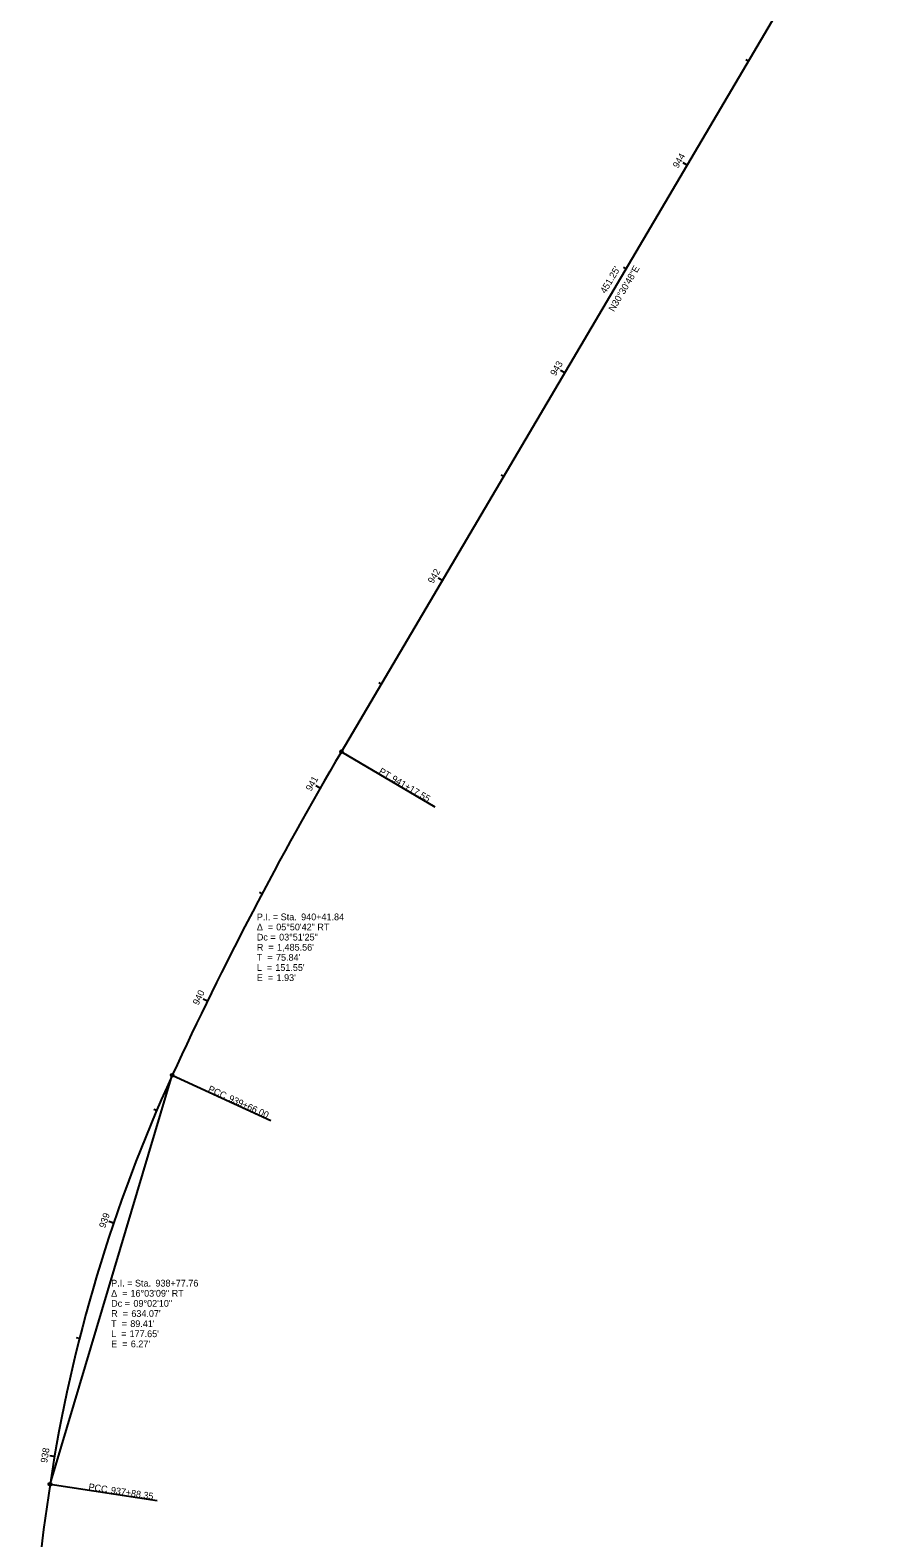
# Model space of a CAD drawing. Extents: x 1978725 to 1979446, y 230316 to 232755.
# Drawn here: x 1978788 to 1979146, y 231522 to 232148 of the extents above; entities that cross this region are included whole.
import ezdxf

# ---------------------------------------------------------------- set-up
doc = ezdxf.new("R2010")
doc.units = 0
for name, color, linetype in [('GE_X_Alignment', 7, 'Continuous'), ('GE_X_Alignment_1000_Curve_Data', 7, 'Continuous'), ('GE_X_Alignment_1000_Stations', 7, 'Continuous'), ('GE_X_Alignment_100_Curve_Data', 7, 'Continuous'), ('GE_X_Alignment_100_Stations', 7, 'Continuous'), ('GE_X_Alignment_500_Curve_Data', 7, 'Continuous'), ('GE_X_Alignment_500_Stations', 7, 'Continuous'), ('SC_Scratch1', 7, 'Continuous')]:
    doc.layers.add(name, color=color, linetype=linetype)

msp = doc.modelspace()

# ---------------------------------------------------------------- linework, layer by layer
at = {"layer": 'GE_X_Alignment'}
msp.add_line((1978917.16, 231848.52), (1979146.28, 232237.28), dxfattribs=at)
for centre, radius, start, end in [((1980196.99, 231094.24), 1485.56, 149.48656, 155.33165), ((1979423.21, 231449.62), 634.07, 155.33165, 171.38409), ((1979695.72, 231408.33), 909.69, 171.38409, 176.17086)]:
    msp.add_arc(centre, radius, start, end, dxfattribs=at)
at = {"layer": 'GE_X_Alignment_1000_Stations'}
for p, q in [((1978917.16, 231848.52), (1978955.93, 231825.67)), ((1978861.55, 231745), (1978859.75, 231745.87)), ((1978847, 231714.26), (1978887.9, 231695.48)), ((1978796.29, 231544.61), (1978840.78, 231537.87))]:
    msp.add_line(p, q, dxfattribs=at)
for centre in [(1978917.16, 231848.52), (1978847, 231714.26), (1978796.29, 231544.61)]:
    msp.add_circle(centre, 0.6, dxfattribs=at)
at = {"layer": 'GE_X_Alignment_100_Stations'}
for p, q in [((1979085.96, 232134.93), (1979084.93, 232135.54)), ((1979060.58, 232091.85), (1979058.85, 232092.87)), ((1979035.19, 232048.78), (1979034.15, 232049.39)), ((1979009.8, 232005.7), (1979008.08, 232006.72)), ((1978984.41, 231962.63), (1978983.38, 231963.24)), ((1978959.03, 231919.55), (1978957.3, 231920.57)), ((1978933.64, 231876.48), (1978932.61, 231877.09)), ((1978917.16, 231848.52), (1978955.93, 231825.67)), ((1978908.34, 231833.35), (1978906.61, 231834.34)), ((1978884.2, 231789.57), (1978883.14, 231790.13)), ((1978861.55, 231745), (1978859.75, 231745.87)), ((1978847, 231714.26), (1978887.9, 231695.48)), ((1978840.51, 231699.64), (1978839.41, 231700.11)), ((1978822.63, 231652.96), (1978820.73, 231653.6)), ((1978808.47, 231605.02), (1978807.31, 231605.31)), ((1978798.14, 231556.11), (1978796.17, 231556.45)), ((1978796.29, 231544.61), (1978840.78, 231537.87))]:
    msp.add_line(p, q, dxfattribs=at)
for centre in [(1978917.16, 231848.52), (1978847, 231714.26), (1978796.29, 231544.61)]:
    msp.add_circle(centre, 0.6, dxfattribs=at)
at = {"layer": 'GE_X_Alignment_500_Stations'}
for p, q in [((1979060.58, 232091.85), (1979059.54, 232092.46)), ((1979009.8, 232005.7), (1979008.77, 232006.31)), ((1978959.03, 231919.55), (1978957.99, 231920.16)), ((1978917.16, 231848.52), (1978955.93, 231825.67)), ((1978908.34, 231833.35), (1978907.3, 231833.95)), ((1978861.55, 231745), (1978859.75, 231745.87)), ((1978847, 231714.26), (1978887.9, 231695.48)), ((1978822.63, 231652.96), (1978821.49, 231653.35)), ((1978798.14, 231556.11), (1978796.96, 231556.31)), ((1978796.29, 231544.61), (1978840.78, 231537.87))]:
    msp.add_line(p, q, dxfattribs=at)
for centre in [(1978917.16, 231848.52), (1978847, 231714.26), (1978796.29, 231544.61)]:
    msp.add_circle(centre, 0.6, dxfattribs=at)
at = {"layer": 'SC_Scratch1'}
msp.add_line((1978796.29, 231544.61), (1978847, 231714.26), dxfattribs=at)

# ---------------------------------------------------------------- texts
at = {"layer": 'GE_X_Alignment_1000_Curve_Data'}
for s, p in [('P.I. = Sta. ', (1978882.08, 231778.59)), ('940+41.84', (1978900.45, 231778.59)), ('Δ  = ', (1978882.08, 231774.39)), ('Dc = ', (1978882.08, 231770.19)), ('05°50\'42" RT', (1978890.11, 231774.39)), ('03°51\'25"', (1978891.32, 231770.19)), ('R  = ', (1978882.08, 231765.99)), ("1,485.56'", (1978890.45, 231765.99)), ('T  = ', (1978882.08, 231761.79)), ('L  = ', (1978882.08, 231757.59)), ("151.55'", (1978889.73, 231757.59)), ("75.84'", (1978890.02, 231761.79)), ('E  = ', (1978882.08, 231753.39)), ("1.93'", (1978890.24, 231753.39)), ('P.I. = Sta. ', (1978821.65, 231626.64)), ('938+77.76', (1978840.02, 231626.64)), ('Δ  = ', (1978821.65, 231622.44)), ('16°03\'09" RT', (1978829.67, 231622.44)), ('Dc = ', (1978821.65, 231618.24)), ('R  = ', (1978821.65, 231614.04)), ("634.07'", (1978830.02, 231614.04)), ('09°02\'10"', (1978830.89, 231618.24)), ('T  = ', (1978821.65, 231609.84)), ("89.41'", (1978829.58, 231609.84)), ('L  = ', (1978821.65, 231605.64)), ('E  = ', (1978821.65, 231601.44)), ("177.65'", (1978829.29, 231605.64)), ("6.27'", (1978829.8, 231601.44))]:
    msp.add_text(s, height=2.8, dxfattribs=at).set_placement(p)
at = {"layer": 'GE_X_Alignment_1000_Stations'}
for s, rotation, p in [("451.25'", 59.48656, (1979026.71, 232038.33)), ('N30°30\'48"E', 59.48656, (1979030.18, 232030.83)), ('PT', 329.48656, (1978932.37, 231839.61)), ('941+17.55', 329.48656, (1978937.62, 231836.52)), ('940', 64.02027, (1978857.82, 231743.16)), ('PCC', 335.33165, (1978861.57, 231707.62)), ('939+66.00', 335.33165, (1978870.07, 231703.72)), ('PCC', 351.38409, (1978812.12, 231542.26)), ('937+88.35', 351.38409, (1978821.36, 231540.86))]:
    msp.add_text(s, height=2.8, rotation=rotation, dxfattribs=at).set_placement(p)
at = {"layer": 'GE_X_Alignment_100_Curve_Data'}
for s, p in [('P.I. = Sta. ', (1978882.08, 231778.59)), ('940+41.84', (1978900.45, 231778.59)), ('Δ  = ', (1978882.08, 231774.39)), ('Dc = ', (1978882.08, 231770.19)), ('05°50\'42" RT', (1978890.11, 231774.39)), ('03°51\'25"', (1978891.32, 231770.19)), ('R  = ', (1978882.08, 231765.99)), ("1,485.56'", (1978890.45, 231765.99)), ('T  = ', (1978882.08, 231761.79)), ('L  = ', (1978882.08, 231757.59)), ("151.55'", (1978889.73, 231757.59)), ("75.84'", (1978890.02, 231761.79)), ('E  = ', (1978882.08, 231753.39)), ("1.93'", (1978890.24, 231753.39)), ('P.I. = Sta. ', (1978821.65, 231626.64)), ('938+77.76', (1978840.02, 231626.64)), ('Δ  = ', (1978821.65, 231622.44)), ('16°03\'09" RT', (1978829.67, 231622.44)), ('Dc = ', (1978821.65, 231618.24)), ('R  = ', (1978821.65, 231614.04)), ("634.07'", (1978830.02, 231614.04)), ('09°02\'10"', (1978830.89, 231618.24)), ('T  = ', (1978821.65, 231609.84)), ("89.41'", (1978829.58, 231609.84)), ('L  = ', (1978821.65, 231605.64)), ('E  = ', (1978821.65, 231601.44)), ("177.65'", (1978829.29, 231605.64)), ("6.27'", (1978829.8, 231601.44))]:
    msp.add_text(s, height=2.8, dxfattribs=at).set_placement(p)
at = {"layer": 'GE_X_Alignment_100_Stations'}
for s, rotation, p in [('944', 59.48656, (1979056.74, 232090.36)), ("451.25'", 59.48656, (1979026.71, 232038.33)), ('N30°30\'48"E', 59.48656, (1979030.18, 232030.83)), ('943', 59.48656, (1979005.95, 232004.18)), ('942', 59.48656, (1978955.17, 231918.02)), ('PT', 329.48656, (1978932.37, 231839.61)), ('941', 60.16343, (1978904.59, 231831.92)), ('941+17.55', 329.48656, (1978937.62, 231836.52)), ('940', 64.02027, (1978857.82, 231743.16)), ('PCC', 335.33165, (1978861.57, 231707.62)), ('939+66.00', 335.33165, (1978870.07, 231703.72)), ('939', 71.29541, (1978819.17, 231650.7)), ('938', 80.33161, (1978795.08, 231553.31)), ('PCC', 351.38409, (1978812.12, 231542.26)), ('937+88.35', 351.38409, (1978821.36, 231540.86))]:
    msp.add_text(s, height=2.8, rotation=rotation, dxfattribs=at).set_placement(p)
at = {"layer": 'GE_X_Alignment_500_Curve_Data'}
for s, p in [('P.I. = Sta. ', (1978882.08, 231778.59)), ('940+41.84', (1978900.45, 231778.59)), ('Δ  = ', (1978882.08, 231774.39)), ('Dc = ', (1978882.08, 231770.19)), ('05°50\'42" RT', (1978890.11, 231774.39)), ('03°51\'25"', (1978891.32, 231770.19)), ('R  = ', (1978882.08, 231765.99)), ("1,485.56'", (1978890.45, 231765.99)), ('T  = ', (1978882.08, 231761.79)), ('L  = ', (1978882.08, 231757.59)), ("151.55'", (1978889.73, 231757.59)), ("75.84'", (1978890.02, 231761.79)), ('E  = ', (1978882.08, 231753.39)), ("1.93'", (1978890.24, 231753.39)), ('P.I. = Sta. ', (1978821.65, 231626.64)), ('938+77.76', (1978840.02, 231626.64)), ('Δ  = ', (1978821.65, 231622.44)), ('16°03\'09" RT', (1978829.67, 231622.44)), ('Dc = ', (1978821.65, 231618.24)), ('R  = ', (1978821.65, 231614.04)), ("634.07'", (1978830.02, 231614.04)), ('09°02\'10"', (1978830.89, 231618.24)), ('T  = ', (1978821.65, 231609.84)), ("89.41'", (1978829.58, 231609.84)), ('L  = ', (1978821.65, 231605.64)), ('E  = ', (1978821.65, 231601.44)), ("177.65'", (1978829.29, 231605.64)), ("6.27'", (1978829.8, 231601.44))]:
    msp.add_text(s, height=2.8, dxfattribs=at).set_placement(p)
at = {"layer": 'GE_X_Alignment_500_Stations'}
for s, rotation, p in [("451.25'", 59.48656, (1979026.71, 232038.33)), ('N30°30\'48"E', 59.48656, (1979030.18, 232030.83)), ('PT', 329.48656, (1978932.37, 231839.61)), ('941+17.55', 329.48656, (1978937.62, 231836.52)), ('940', 64.02027, (1978857.82, 231743.16)), ('PCC', 335.33165, (1978861.57, 231707.62)), ('939+66.00', 335.33165, (1978870.07, 231703.72)), ('PCC', 351.38409, (1978812.12, 231542.26)), ('937+88.35', 351.38409, (1978821.36, 231540.86))]:
    msp.add_text(s, height=2.8, rotation=rotation, dxfattribs=at).set_placement(p)

doc.saveas('drawing.dxf')
